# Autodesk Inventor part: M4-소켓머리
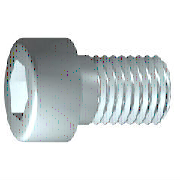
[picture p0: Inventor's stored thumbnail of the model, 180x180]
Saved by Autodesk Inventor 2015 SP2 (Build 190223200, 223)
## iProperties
IsCustomPart: 0
Created: 2009-02
Part Number: M4-소켓머리
Material: 강, 연강
Description: 6각머리 태핑 나사
Document SubType Name: Modeling
Standard: KS B 1003
Designer: 한국산업디자인학원 [http://gmhk.co.kr]
Standards Organization: KS
Language: ko-KR
Size Designation: M 4 x 12
Categories: <MemberInstance><Categories><Category DisplayName="조임쇠" InternalName="e4da775c-781d-43d5-af7c-5136215cf5a6" Mnemonic="FSTN"><Category DisplayName="볼트" InternalN
Density: 7.85 g/cm^3
Appearance: _시험-금속-강(연마)
Mass: 2.2318 g
Surface Area: 3.30853 cm^2
Volume: 0.284306 cm^3
Author: pww
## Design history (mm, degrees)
sketch "스케치1"
  geometry: L1 (-1, 0)-(12, 0); L2 (12, 0)-(12, 2); L3 (12, 2)-(1.75, 2); L4 (1.75, 2)-(1.32, 2); L5 (1.32, 2)-(0, 2); L6 (0, 2)-(0, 3.5); L7 (0, 3.5)-(-4, 3.5); L8 (-4, 3.5)-(-4, 1.732); L9 (-4, 1.732)-(-2, 1.732); L10 (-2, 1.732)-(-1, 0); L11 (-7.2, 0)-(15.2, 0) reference; L12 (0, -0.7)-(0, 4.2) reference; L13 (1.75, 2)-(0, 2)
  constraints: 22 end point, 6 parallel, 2 collinear, 2 perpendicular, 1 horizontal, 1 point on line
  dimensions: "d1" = 10.25 distance from line of L3.end L2 (= GEL); "d2" = 0.42952 distance of L4.end L3.end (computed from GAL); "d3" = 4 distance between parallel lines of L8 L6 (= KOH); "d4" = 2 distance of L8.end L9.end (= INTI); "d5" = 60 deg angle of L10 L1; "d6" = 4 diameter of L3 L1 (= GD); "d7" = 4 diameter of L5 L1 (= BDM); "d8" = 3.4641 diameter of L9 L1 (= 1.1547 x SW); "d9" = 7 diameter of L7 L1 (= KOD); "d26" = 12 distance between parallel lines of L12 L2 (= NLG)
revolve "본체" sketch "스케치1" stored, may be unused: angle "d10" = 90 deg
sketch "스케치2"
  geometry: L1 (0, -4.9)-(0, 4.9) reference; L2 (-4.9, 0)-(4.9, 0) reference; L3 (1.732, 0)-(0.866, -1.5); L4 (0.866, -1.5)-(-0.866, -1.5); L5 (-0.866, -1.5)-(-1.732, 0); L6 (-1.732, 0)-(-0.866, 1.5); L7 (-0.866, 1.5)-(0.866, 1.5); L8 (0.866, 1.5)-(1.732, 0); 2 further points
  constraints: 12 end point, 1 coincident, 1 horizontal alignment, 1 point on line, 12 other
extrude "슬롯" join sketch "스케치2" stored distance "d11" = 10; taper "d12" = 0 deg
workplane "Work Plane1"
fillet "Fillet2" dims "d30" = 0.1 (= R)
body "Solid1"
fillet "모깎기1" dims "d17" = 0.4 (= RR)
feature "스레드" dims "d13" = 10.25 (= GEL), "d14" = 0
chamfer "모따기1" distance "d15" = 0.42941 (= -0.5 x SPD + 0.5 x GD); stored, may be unused: second distance "d16" = 0.42941 (= GUL), angle "d27" = 45 deg
other parameters: "GD" = 4 (= NND) [user parameter; used in 2 equation terms], "NLG" = 12 [user parameter; used in 1 equation term], "GEL" = 10.25 [user parameter; used in 2 equation terms], "KOD" = 7 [user parameter; used in 1 equation term], "KOH" = 4 [user parameter; used in 1 equation term], "INTI" = 2 [user parameter; used in 1 equation term], "GAL" = 0.42941 (= 0.61345 x PTC) [user parameter; used in 1 equation term], "GUL" = 0.42941 (= 0.61345 x PTC) [user parameter; used in 1 equation term], "BDM" = 4 (= NND) [user parameter; used in 1 equation term], "SW" = 3 [user parameter; used in 2 equation terms], "RR" = 0.4 [user parameter; used in 1 equation term], "SPD" = 3.14117 (= NND - 1.2269 x PTC) [user parameter; used in 1 equation term], "d19" = 0, "d28" = 0, "d29" = 0, "R" = 0.1 [user parameter; used in 1 equation term], "PHH" = 0.2 [user parameter], "GD1" = 3.14117 (= THREADDIA - 1.2269 x PTC) [user parameter], "THREADDIA" = 4 [user parameter; used in 1 equation term], "FAWI" = 45 deg [user parameter], "TPU" = 14.28571 (computed from PTC) [user parameter], "PTC" = 0.7 [user parameter; used in 5 equation terms], "NND" = 4 [user parameter; used in 3 equation terms], "TOA" = 30 deg [user parameter], "E0" = 3.465 (= 1.155 x SW) [user parameter]
